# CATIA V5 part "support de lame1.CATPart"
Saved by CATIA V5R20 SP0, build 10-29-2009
Part number: 3
Bounding box of the stored display mesh (mm): x -57 to 7, y -25 to 25, z 0 to 65
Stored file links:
  C:\Users\halimelbaba\Documents\cmv\projet\support de lame1.CATPart
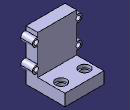
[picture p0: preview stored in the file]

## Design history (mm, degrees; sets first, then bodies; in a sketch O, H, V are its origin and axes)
Body1 (main body)
  Sketch1 on xy-plane, origin (0, 0, 0), H (1, 0, 0), V (0, 1, 0)
    line L1 (-50, 25) -> (0, 25)
    line L2 (0, 25) -> (0, -25)
    line L3 (0, -25) -> (-50, -25)
    line L4 (-50, -25) -> (-50, 25)
    distance L4 L2 = 50
    distance L3 L1 = 50
    horizontal: L1 H, L3 H
    vertical: L2 V, L4 V
    coincidence: L2 V
    symmetry: L3 L1 H
  Pad1: profile Sketch1, direction (0, 0, 1), length 15
  Plane1: type Offset, RefPlane end face of Pad1, Offset 0, reversed
  Sketch2 on end face of Pad1, origin (0, 0, 15), H (1, 0, 0), V (0, 1, 0)
    line L1 (-50, -10) -> (0, -10)
    line L2 (0, -10) -> (0, -25)
    line L3 (0, -25) -> (-50, -25)
    line L4 (-50, -25) -> (-50, -10)
    reference projected line E1 (-50, -25) -> (0, -25) from edge [face of Pad1 from Sketch1.L3 | end face of Pad1]
    reference projected line E2 (0, -25) -> (0, 25) from edge [face of Pad1 from Sketch1.L2 | end face of Pad1]
    reference projected line E3 (-50, 25) -> (-50, -25) from edge [face of Pad1 from Sketch1.L4 | end face of Pad1]
    distance L1 L3 = 15
    horizontal: L1 H, L3 H
    vertical: L2 V, L4 V
    coincidence: L3 E1, L2 E2, L4 E3
  Pad2: profile Sketch2, direction (0, 0, 1), length 50
  Plane2: type Offset, RefPlane face of Pad2, Offset 0, reversed
  Sketch3 on face of Pad2, origin (0, -25, 0), H (1, 0, 0), V (0, 0, 1)
    circle A1 centre (2, 55) radius 5
    point P1 (2, 55)
    reference projected line E1 (0, 0) -> (0, 15) from edge [face of Pad2 | face of Pad2]
    reference projected line E2 (-50, 65) -> (0, 65) from edge [face of Pad2 | end face of Pad2]
    circle A2 centre (-52, 55) radius 5
    point P2 (-52, 55)
    reference projected line E3 (-50, 65) -> (0, 65) from edge [face of Pad2 | end face of Pad2]
    reference projected line E4 (-50, 0) -> (-50, 15) from edge [face of Pad2 | face of Pad2]
    point P3 (-44.3226, 0)
    circle A3 centre (-52, 25) radius 5
    point P4 (-52, 25)
    reference projected line E5 (-50, 0) -> (-50, 15) from edge [face of Pad2 | face of Pad2]
    reference projected line E6 (-50, 0) -> (0, 0) from edge [start face of Pad1 | face of Pad2]
    circle A4 centre (2, 25) radius 5
    point P5 (2, 25)
    reference projected line E7 (-50, 0) -> (0, 0) from edge [start face of Pad1 | face of Pad2]
    reference projected line E8 (0, 0) -> (0, 15) from edge [face of Pad2 | face of Pad2]
    distance P1 E1 = 2
    distance P1 E2 = 10
    radius A1 = 5
    distance P2 E3 = 10
    distance P2 E4 = 2
    radius A2 = 5
    distance P4 E5 = 2
    radius A3 = 5
    distance P4 E6 = 25
    distance P5 E7 = 25
    radius A4 = 5
    distance P5 E8 = 2
    coincidence: P3 H
  Pad3: profile Sketch3, direction (0, 1, 0), up to face of Pad2 from Sketch2.L1
  Sketch4 on face of Pad2, origin (-7.5024, -25, 54.4561), H (1, 0, 0), V (0, 0, 1)
    point P1 (9.5024, 0.5439)
    reference projected circle E1 centre (9.5024, 0.5439) radius 5 from edge [face of Pad3 from Sketch3.A1 | face of Pad2]
    concentricity: P1 E1
  Hole1: placed by Sketch4, at (2, -25, 55) direction (0, 1, 0), diameter 6, up to face of Pad2
  Sketch5 on face of Pad2, origin (3.3216, -25, 26.4177), H (1, 0, 0), V (0, 0, 1)
    point P1 (-1.3216, -1.4177)
    reference projected circle E1 centre (-1.3216, -1.4177) radius 5 from edge [face of Pad3 from Sketch3.A4 | face of Pad2]
    concentricity: P1 E1
  Hole2: placed by Sketch5, at (2, -25, 25) direction (0, 1, 0), diameter 6, up to face of Pad2
  Sketch6 on face of Pad2, origin (-27.6498, -25, 45.543), H (1, 0, 0), V (0, 0, 1)
    point P1 (-24.3502, 9.457)
    reference projected circle E1 centre (-24.3502, 9.457) radius 5 from edge [face of Pad3 from Sketch3.A2 | face of Pad2]
    concentricity: P1 E1
  Hole3: placed by Sketch6, at (-52, -25, 55) direction (0, 1, 0), diameter 6, up to face of Pad2
  Sketch7 on face of Pad2, origin (-44.0968, -25, 29.5826), H (1, 0, 0), V (0, 0, 1)
    point P1 (-7.9032, -4.5826)
    reference projected circle E1 centre (-7.9032, -4.5826) radius 5 from edge [face of Pad3 from Sketch3.A3 | face of Pad2]
    concentricity: P1 E1
  Hole4: placed by Sketch7, at (-52, -25, 25) direction (0, 1, 0), diameter 6, up to face of Pad2
  Sketch8 on end face of Pad1, origin (-41.3366, 10.9957, 15), H (1, 0, 0), V (0, 1, 0)
    point P1 (1.3366, -0.9957)
    reference projected line E1 (41.3366, 14.0043) -> (-8.6634, 14.0043) from edge [face of Pad1 from Sketch1.L1 | end face of Pad1]
    reference projected line E2 (-8.6634, 14.0043) -> (-8.6634, -35.9957) from edge [face of Pad2 | end face of Pad1]
    distance P1 E1 = 15
    distance P1 E2 = 10
  Hole5: placed by Sketch8, at (-40, 10, 15) direction (0, 0, -1), diameter 10, up to start face of Pad1
  Sketch9 on end face of Pad1, origin (-18.7285, 9.4346, 15), H (1, 0, 0), V (0, 1, 0)
    point P1 (8.7285, 0.5654)
    reference projected line E1 (18.7285, -34.4346) -> (18.7285, 15.5654) from edge [face of Pad2 | end face of Pad1]
    reference projected line E2 (18.7285, 15.5654) -> (-31.2715, 15.5654) from edge [face of Pad1 from Sketch1.L1 | end face of Pad1]
    distance P1 E1 = 10
    distance P1 E2 = 15
  Hole6: placed by Sketch9, at (-10, 10, 15) direction (0, 0, -1), diameter 10, up to start face of Pad1
  Sketch10 on end face of Pad1, origin (-25.1212, 7.5024, 15), H (1, 0, 0), V (0, 1, 0)
    point P1 (15.1212, 2.4976)
    reference projected circle E1 centre (15.1212, 2.4976) radius 5 from edge [end face of Pad1 | face of Hole6]
    concentricity: P1 E1
  Hole7: placed by Sketch10, at (-10, 10, 15) direction (0, 0, -1), diameter 14, depth 4
  Sketch11 on end face of Pad1, origin (-30.6696, 3.3789, 15), H (1, 0, 0), V (0, 1, 0)
    point P1 (-9.3304, 6.6211)
    reference projected circle E1 centre (-9.3304, 6.6211) radius 5 from edge [end face of Pad1 | face of Hole5]
    reference projected circle E2 centre (-9.3304, 6.6211) radius 5 from edge [end face of Pad1 | face of Hole5]
    concentricity: E1 P1, P1 E2
  Hole8: placed by Sketch11, at (-40, 10, 15) direction (0, 0, -1), diameter 14, depth 4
